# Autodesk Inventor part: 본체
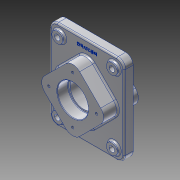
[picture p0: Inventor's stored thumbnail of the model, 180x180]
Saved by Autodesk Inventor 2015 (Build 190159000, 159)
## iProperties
Created: 2026-07
Part Number: 본체
Material: 알루미늄 6061
Document SubType Name: Modeling
Designer: USER
Density: 2.7 g/cm^3
Appearance: 알루미늄 - 평지
Mass: 2132.56 g
Surface Area: 957.082 cm^2
Volume: 789.839 cm^3
Author: USER
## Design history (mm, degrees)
sketch "스케치1"
  geometry: L1 (75, 90)-(-75, 90); L2 (-75, 90)-(-75, -90); L3 (-75, -90)-(75, -90); L4 (75, -90)-(75, 90); L5 (75, 90)-(-75, -90); L6 (-75, 90)-(75, -90); 1 further point
  constraints: 12 end point, 2 midpoint, 2 parallel, 1 horizontal, 1 perpendicular
  dimensions: "d0" = 150 distance of L3.end L2.end; "d1" = 180 distance of L2.end L1.end
extrude "돌출1" new body sketch "스케치1" stored distance "d2" = 18; taper "d3" = 0 deg
sketch "스케치2"
  geometry: L1 (-14.142, 56.569)-(-56.569, 14.142); L2 (-56.569, -14.142)-(-14.142, -56.569); L3 (14.142, -56.569)-(56.569, -14.142); L4 (56.569, 14.142)-(14.142, 56.569); A1 r 20 centre (0, 42.426) between (14.142, 56.569) and (-14.142, 56.569); A2 r 20 centre (-42.426, 0) between (-56.569, 14.142) and (-56.569, -14.142); A3 r 20 centre (42.426, 0) between (56.569, -14.142) and (56.569, 14.142); A4 r 20 centre (0, -42.426) between (-14.142, -56.569) and (14.142, -56.569); 5 further points
  constraints: 8 end point, 8 point on circle, 8 point on line, 8 tangent, 4 centre point, 3 equal radius, 2 horizontal alignment, 2 parallel, 2 vertical alignment
  dimensions: "d6" = 100 distance between parallel lines of L3 L1; "d7" = 100 distance of point (0, 70.711) point (-70.711, 0); "d8" = 20 radius of A1
extrude "돌출2" join sketch "스케치2" distance "d9" = 29; taper "d10" = 0 deg
sketch "스케치3"
  geometry: L1 (-56.569, -14.142)-(-14.142, -56.569) reference; L2 (14.142, -56.569)-(56.569, -14.142) reference; L3 (56.569, 14.142)-(14.142, 56.569) reference; L4 (-14.142, 56.569)-(-56.569, 14.142) reference; A1 r 20 centre (0, -42.426) between (-14.142, -56.569) and (14.142, -56.569) reference; A2 r 20 centre (42.426, 0) between (56.569, -14.142) and (56.569, 14.142) reference; A3 r 20 centre (0, 42.426) between (14.142, 56.569) and (-14.142, 56.569) reference; A4 r 20 centre (-42.426, 0) between (-56.569, 14.142) and (-56.569, -14.142) reference; 1 further point
extrude "돌출3" join sketch "스케치3" distance "d11" = 23; taper "d12" = 0 deg
fillet "모깎기1" dims "d13" = 15
hole "구멍2" diameter "d34" = 54; stored, may be unused: countersink angle "d38" = 90 deg, drill point angle "d40" = 0 deg; dims "d32" = 50, "d33" = 50, "d35" = 6, "d36" = 62, "d37" = 22, "d39" = 8
sketch "스케치6"
  geometry: L1 (-60, 90)-(60, 90) reference; L2 (75, 75)-(75, -75) reference; L3 (60, -90)-(-60, -90) reference; L4 (-75, -75)-(-75, 75) reference; L5 (14.142, 56.569)-(56.569, 14.142) reference; L6 (56.569, -14.142)-(14.142, -56.569) reference; L7 (-14.142, -56.569)-(-56.569, -14.142) reference; L8 (-56.569, 14.142)-(-14.142, 56.569) reference; L9 (-55, 70)-(55, 70); L10 (55, 70)-(55, -70); L11 (55, -70)-(-55, -70); L12 (-55, -70)-(-55, 70); C1 r 27 at (0, 0) reference; C2 r 11 at (-55, 70); A1 r 15 centre (-60, 75) between (-60, 90) and (-75, 75) reference; A2 r 15 centre (60, 75) between (75, 75) and (60, 90) reference; A3 r 15 centre (60, -75) between (60, -90) and (75, -75) reference; A4 r 15 centre (-60, -75) between (-75, -75) and (-60, -90) reference; A5 r 20 centre (0, 42.426) between (14.142, 56.569) and (-14.142, 56.569) reference; A6 r 20 centre (42.426, 0) between (56.569, -14.142) and (56.569, 14.142) reference; A7 r 20 centre (0, -42.426) between (-14.142, -56.569) and (14.142, -56.569) reference; A8 r 20 centre (-42.426, 0) between (-56.569, 14.142) and (-56.569, -14.142) reference; 2 further points
  constraints: 8 end point, 2 parallel, 1 centre point, 1 coincident, 1 horizontal, 1 midpoint, 1 perpendicular, 1 vertical alignment
  dimensions: "d52" = 110 distance of L10.end L11.end; "d53" = 140 distance of L9.end L10.end; "d54" = 20 distance between parallel lines of L9 L1; "d55" = 22 diameter of C2
extrude "돌출5" join sketch "스케치6" distance "d56" = 5; taper "d57" = 0 deg
hole "구멍4" diameter "d60" = 11; stored, may be unused: countersink angle "d64" = 90 deg, drill point angle "d66" = 0 deg; dims "d58" = 10, "d59" = 10, "d61" = 10, "d62" = 62, "d63" = 22, "d65" = 13
chamfer "모따기1" distance "d73" = 1; stored, may be unused: second distance "d74" = 2, angle "d75" = 45 deg
fillet "모깎기2" dims "d76" = 1
fillet "모깎기3" dims "d77" = 3
sketch "스케치7"
  geometry: L1 (60, 90)-(-60, 90) reference; 2 further points
  constraints: 1 vertical alignment, 1 other
  dimensions: "d78" = 15 distance from line of L1 point (0, 75)
feature "엠보싱1" sketch "스케치7" dims "d0" = 150, "d1" = 180, "d79" = 0.5, "d80" = 0
sketch "스케치11"
  geometry: L1 (0, 0)-(-48, 0)
  constraints: 2 end point, 1 horizontal
  dimensions: "d97" = 48 distance of L1.start L1.end
hole "구멍7" sketch "스케치11" at (-48, 0) diameter "d98" = 4.917; stored, may be unused: countersink angle "d102" = 90 deg, drill point angle "d104" = 118 deg; dims "d99" = 10, "d100" = 62, "d101" = 22, "d103" = 13
sketch "스케치13"
  geometry: 1 further point
hole "구멍9" sketch "스케치13" at (0, 0) diameter "d119" = 62; stored, may be unused: countersink angle "d123" = 90 deg, drill point angle "d125" = 0 deg; dims "d120" = 10, "d121" = 62, "d122" = 22, "d124" = 22
sketch "스케치14"
  geometry: L1 (0, 0)-(0, -48); C1 r 2.458 at (0, -48) reference
  constraints: 2 end point, 1 vertical
  dimensions: "d126" = 48 distance of L1.start L1.end (derived)
hole "구멍10" sketch "스케치14" at (0, -48) diameter "d127" = 4.917; stored, may be unused: countersink angle "d131" = 90 deg, drill point angle "d133" = 118 deg; dims "d128" = 10, "d129" = 62, "d130" = 22, "d132" = 13
fillet "모깎기4" dims "d137" = 1
chamfer "모따기2" distance "d138" = 1; stored, may be unused: second distance "d139" = 2, angle "d140" = 45 deg
node "솔리드1"
pattern_linear "직사각형 패턴2"
pattern_circular "원형 패턴2" dims angle "d106" = 360 deg
pattern_circular "원형 패턴4" dims angle "d135" = 360 deg
node "절단 모서리 투영1"
